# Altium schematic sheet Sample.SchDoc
size A3; SheetNumber: 3; SheetTotal: 4
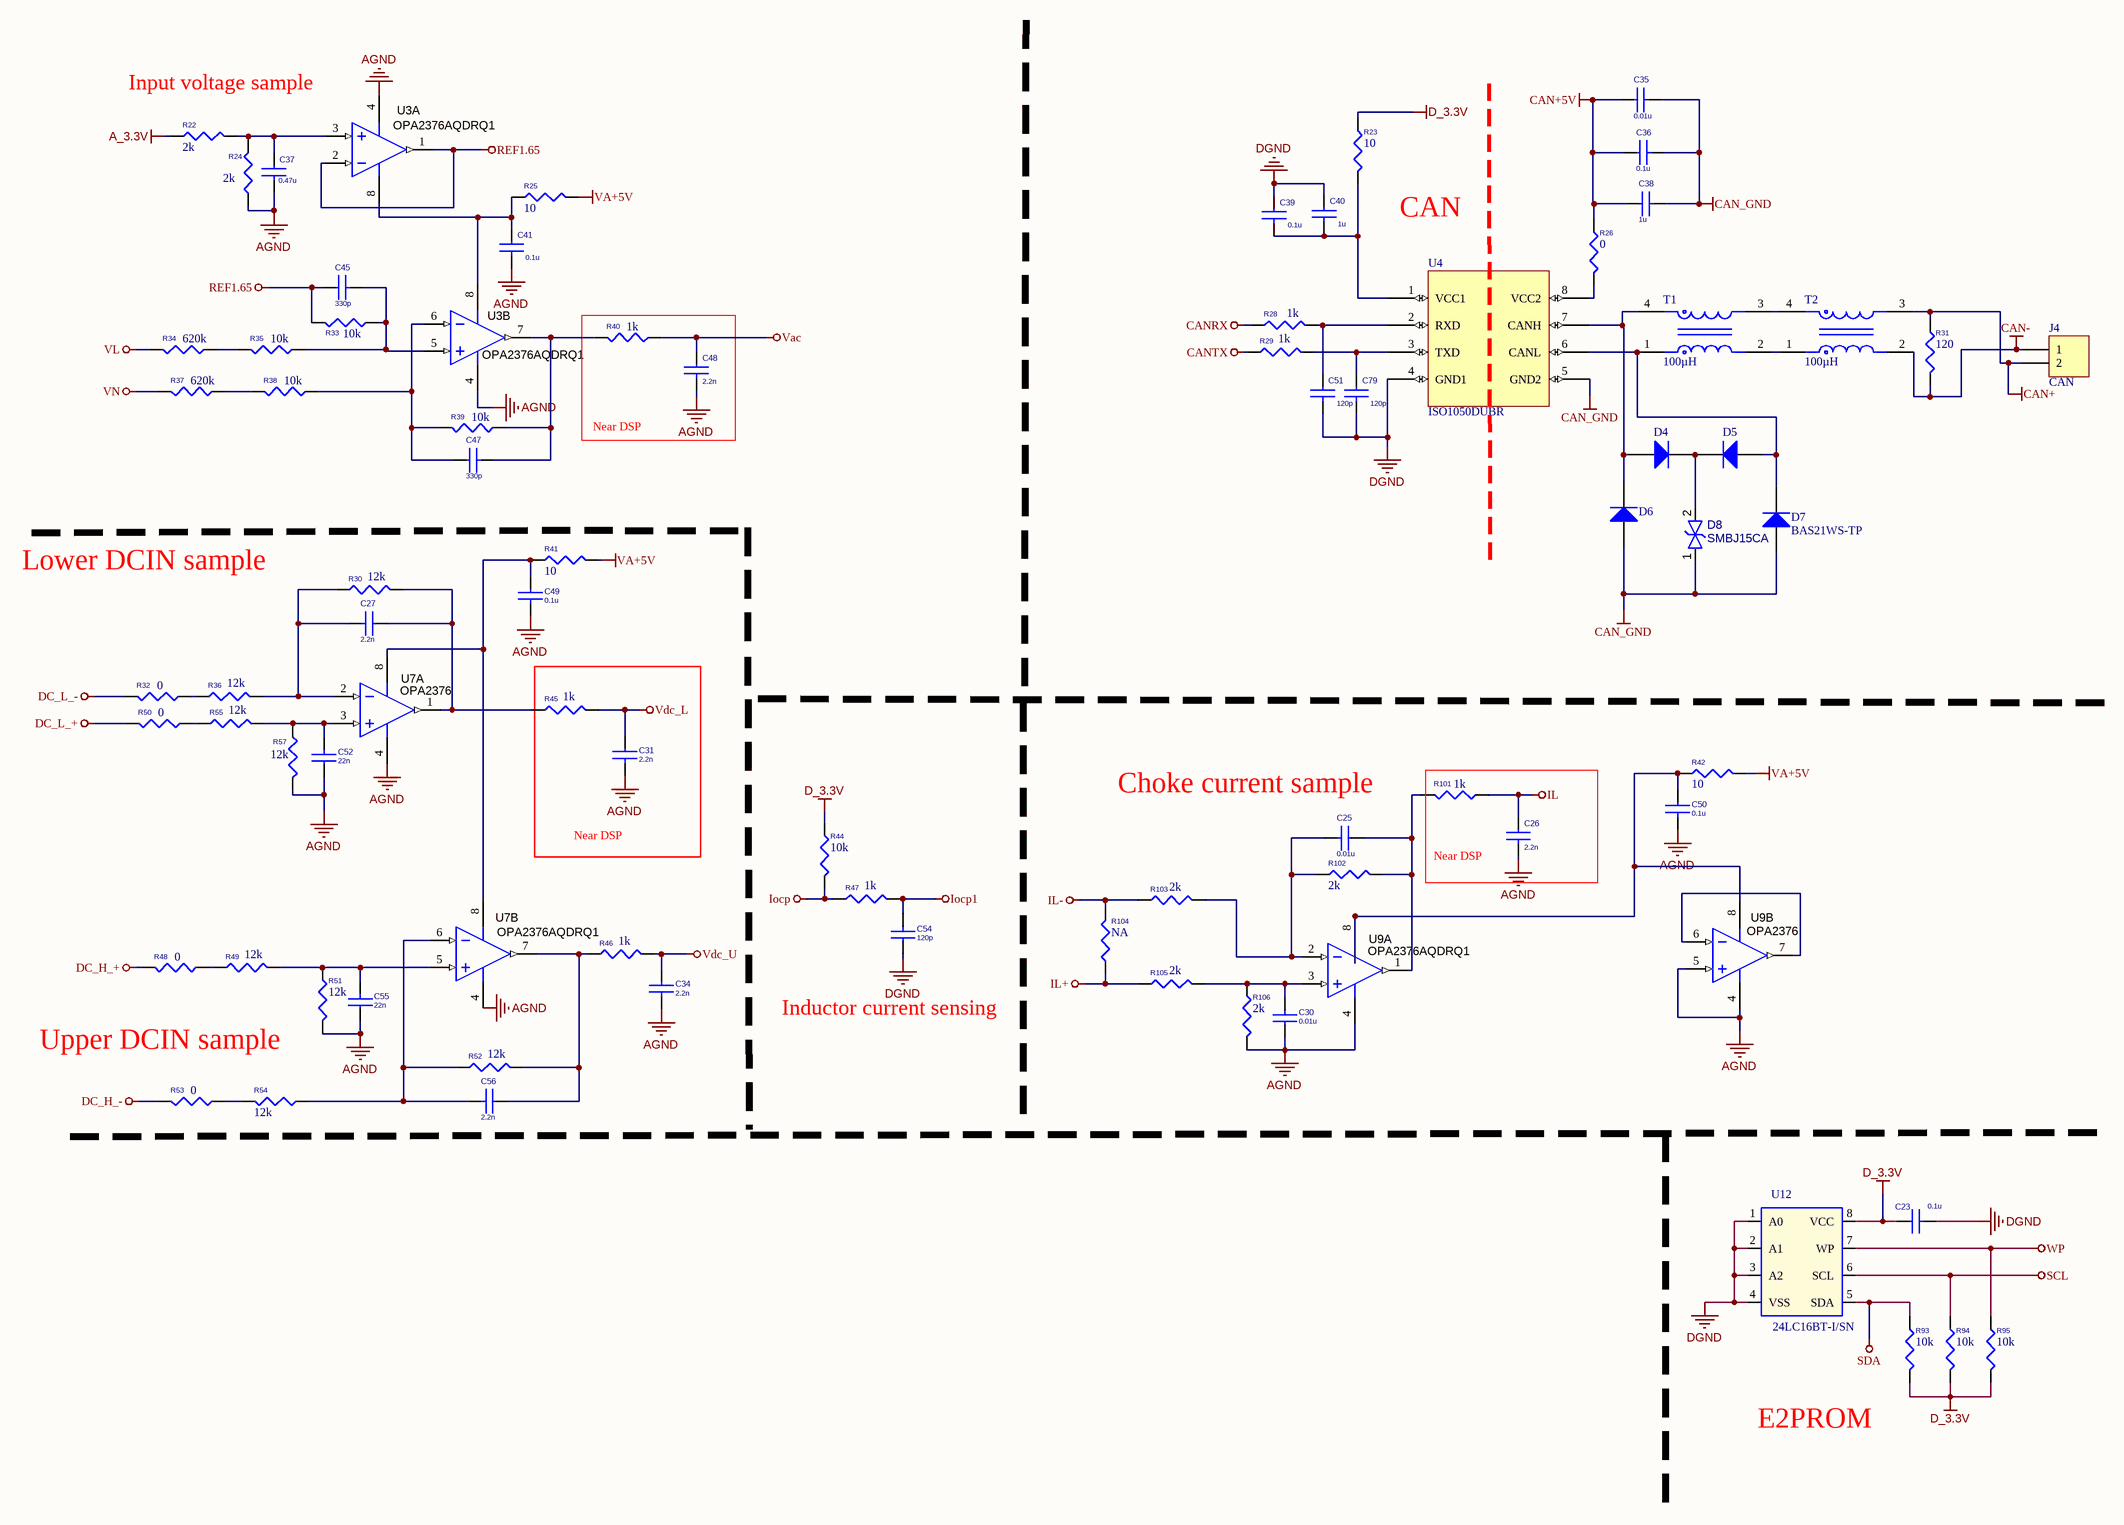
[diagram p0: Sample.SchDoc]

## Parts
C23  0.1u  [C0402]
C25  0.01u  [C0402]
C26  2.2n  [C0402]
C27  2.2n  [C0402]
C30  0.01u  [C0402]
C31  2.2n  [C0402]
C34  2.2n  [C0402]
C35  0.01u  [C0402]
C36  0.1u  [C0402]
C37  0.47u  [C0402]
C38  1u  [C0402]
C39  0.1u  [C0402]
C40  1u  [C0402]
C41  0.1u  [C0402]
C45  330p  [C0402]
C47  330p  [C0402]
C48  2.2n  [C0402]
C49  0.1u  [C0402]
C50  0.1u  [C0402]
C51  120p  [C0402]
C52  22n  [C0402]
C54  120p  [C0402]
C55  22n  [C0402]
C56  2.2n  [C0402]
C79  120p  [C0402]
D4  BAS21WS-TP  [DIOD-SOD323-2-A_V]  (value not drawn)
D5  BAS21WS-TP  [DIOD-SOD323-2-A_V]  (value not drawn)
D6  BAS21WS-TP  [DIOD-SOD323-2-A_V]  (value not drawn)
D7  BAS21WS-TP  [DIOD-SOD323-2-A_V]
D8  SMBJ15CA  [DO214AA]
J4  CAN  [HDR1X2H-254MM]
R22  2k  [R0402]
R23  10  [R0402]
R24  2k  [R0402]
R25  10  [R0402]
R26  0  [R0402]
R28  1k  [R0402]
R29  1k  [R0402]
R30  12k  [R0402]
R31  120  [R0603]
R32  0  [R1206]
R33  10k  [R0402]
R34  620k  [R1206]
R35  10k  [R1206]
R36  12k  [R1206]
R37  620k  [R1206]
R38  10k  [R1206]
R39  10k  [R0402]
R40  1k  [R0402]
R41  10  [R0402]
R42  10  [R0402]
R44  10k  [R0402]
R45  1k  [R0402]
R46  1k  [R0402]
R47  1k  [R0402]
R48  0  [R1206]
R49  12k  [R1206]
R50  0  [R1206]
R51  12k  [R0402]
R52  12k  [R0402]
R53  0  [R1206]
R54  12k  [R1206]
R55  12k  [R1206]
R57  12k  [R0402]
R93  10k  [R0402]
R94  10k  [R0402]
R95  10k  [R0402]
R101  1k  [R0402]
R102  2k  [R0402]
R103  2k  [R0402]
R104  NA  [R0402]
R105  2k  [R0402]
R106  2k  [R0402]
T1  AMCW4532B-2-101T: 100µH  [FP-DLW43-0_2-t2_6-e0_6-MFG]  (hidden comment: DLW43SH101XK2L)
T2  AMCW4532B-2-101T: 100µH  [FP-DLW43-0_2-t2_6-e0_6-MFG]  (hidden comment: DLW43SH101XK2L)
U3  OPA2376AQDRQ1  [8SOIC]  (parts A,B of 2)
U4  ISO1050DUBR  [8-SOP]
U7  OPA2376  [8SOIC]  (parts A,B of 2)
U9  OPA2376AQDRQ1  [8SOIC]  (parts A,B of 2)
U12  24LC16BT-I/SN  [8SOIC]

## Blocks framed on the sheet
Near DSP: C48 R40
Near DSP: C31 R45
Near DSP: C26 R101

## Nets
A_3.3V: R22.1
AGND: C26.2 C30.1 C31.2 C34.2 C37.2 C41.2 C48.2 C49.2 C50.2 C52.1 C55.1 R24.1 R51.2 R57.2 R106.2 U3.4(V-) U7.4(V-) U9.4(V-) U9.5(IN_B+)
CAN+: J4.2 R31.1 T2.3
CAN+5V: C35.1 C36.1 C38.1 R26.1
CAN-: J4.1 R31.2 T2.2
CAN_GND: C35.2 C36.2 C38.2 D6.1(A) D7.1(A) D8.1(A) U4.5(GND2)
CANRX: R28.1
CANTX: R29.1
D_3.3V: C23.1 R23.1 R44.1 R93.2 R94.2 R95.2 U12.8(VCC)
DC_H_+: R48.2
DC_H_-: R53.2
DC_L_+: R50.2
DC_L_-: R32.2
DGND: C23.2 C39.1 C40.1 C51.2 C54.1 C79.2 U4.4(GND1) U12.1(A0) U12.2(A1) U12.3(A2) U12.4(VSS)
IL: C26.1 R101.1
IL+: R104.1 R105.1
IL-: R103.1 R104.2
Iocp: R44.2 R47.1
Iocp1: C54.2 R47.2
REF1.65: C45.1 R33.2 U3.1(OUT_A) U3.2(IN_A-)
SCL: R94.1 U12.6(SCL)
SDA: R93.1 U12.5(SDA)
VA+5V: R25.2 R41.2 R42.2
Vac: C48.1 R40.1
Vdc_L: C31.1 R45.2
Vdc_U: C34.1 R46.2
VL: R34.2
VN: R37.2
WP: R95.1 U12.7(WP)
NetC25_1: C25.1 R101.2 R102.2 U9.1(OUT_A)
NetC25_2: C25.2 R102.1 R103.2 U9.2(IN_A-)
NetC27_1: C27.1 R30.2 R45.1 U7.1(OUT_A)
NetC27_2: C27.2 R30.1 R36.2 U7.2(IN_A-)
NetC30_2: C30.2 R105.2 R106.1 U9.3(IN_A+)
NetC37_1: C37.1 R22.2 R24.2 U3.3(IN_A+)
NetC39_2: C39.2 C40.2 R23.2 U4.1(VCC1)
NetC41_1: C41.1 R25.1 U3.8(V+)
NetC45_2: C45.2 R33.1 R35.1 U3.5(IN_B+)
NetC47_1: C47.1 R38.1 R39.2 U3.6(IN_B-)
NetC47_2: C47.2 R39.1 R40.2 U3.7(OUT_B)
NetC49_1: C49.1 R41.1 U7.8(V+)
NetC50_1: C50.1 R42.1 U9.8(V+)
NetC51_1: C51.1 R28.2 U4.2(RXD)
NetC52_2: C52.2 R55.2 R57.1 U7.3(IN_A+)
NetC55_2: C55.2 R49.2 R51.1 U7.5(IN_B+)
NetC56_1: C56.1 R46.1 R52.2 U7.7(OUT_B)
NetC56_2: C56.2 R52.1 R54.1 U7.6(IN_B-)
NetC79_1: C79.1 R29.2 U4.3(TXD)
NetD4_1: D4.1(A) D6.2(K) T1.4 U4.7(CANH)
NetD4_2: D4.2(K) D5.2(K) D8.2(A)
NetD5_1: D5.1(A) D7.2(K) T1.1 U4.6(CANL)
NetR26_2: R26.2 U4.8(VCC2)
NetR32_1: R32.1 R36.1
NetR34_1: R34.1 R35.2
NetR37_1: R37.1 R38.2
NetR48_1: R48.1 R49.1
NetR50_1: R50.1 R55.1
NetR53_1: R53.1 R54.2
NetT1_2: T1.2 T2.1
NetT1_3: T1.3 T2.4
NetU9_6: U9.6(IN_B-) U9.7(OUT_B)

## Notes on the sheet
- (near U3) Input voltage sample
- CAN
- Lower DCIN sample
- Choke current sample
- Upper DCIN sample
- Inductor current sensing
- E2PROM

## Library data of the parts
C23 = CAP NP_Dup1: CAP CER 0.1UF 25V X7R 0402; PCB Footprint: C0603
C25 C30 C35 = CAP NP_Dup1: CAP CER 0.012UF 25V X7R 0402; PCB Footprint: C1206
C26 C27 C31 C34 C48 C56 = CAP NP_Dup1: CAP CER 2200PF 25V X7R 0402; PCB Footprint: C1206
C36 C39 = CAP NP_Dup1: CCAP CER 0.1UF 25V X7R 0402; PCB Footprint: C1206
C37 = CAP NP_Dup1: CAP CER 0.47UF 25V X5R 0402; PCB Footprint: C1206
C38 C40 = CAP NP_Dup1: CAP CER 1UF 25V X5R 0402; PCB Footprint: C1206
C41 C49 C50 = CAP NP_Dup1: CAP CER 0.1UF 25V X7R 0402; PCB Footprint: C1206
C45 C47 = CAP NP_Dup1: CAP CER 330PF 25V X7R 0402; PCB Footprint: C1206
C51 C54 C79 = CAP NP_Dup1: CAP CER 120PF 25V C0G/NP0 0402; PCB Footprint: C1206
C52 C55 = CAP NP_Dup1: CAP CER 0.022UF 25V X7R 0402; PCB Footprint: C1206
D4-D7 = CMP-004-00002-1: DIODE GEN PURP 250V 200MA SOD323; Manufacturer: Diodes Inc; Peak Reverse Current: 1uA; Forward Voltage: 1.25V; Recovery Time: 4ns; Max Surge Current: 2A; Forward Current: 3dA; Elements: 1
D8 = CMP-004-00030-2: TVS DIODE 15V 24.4V DO214AA; Manufacturer: STMicroelectronics; Manufacturer Part Number: ESDALC5-1BM2
J4 = Header 2H: 1*2P 2.54mm
R22 R102 R103 R105 R106 = RESISTOR_Dup1: RCC0402 100 2K0 1% ET7 E3; PCB Footprint: R0603
R23 R25 R41 R42 = RESISTOR_Dup1: RES 10 OHM 1% 1/8W 0402; PCB Footprint: R0603
R24 = RESISTOR_Dup1: RES 3.9K OHM 1% 1/8W 0402; PCB Footprint: R0603
R26 R104 = RESISTOR_Dup1: PCB Footprint: R0603
R28 R29 R40 R45-R47 R101 = RESISTOR_Dup1: RES 1K OHM 1% 1/8W 0402; PCB Footprint: R0603
R30 R51 R52 R57 = RESISTOR_Dup1: RES 12K OHM 1% 1/8W 0402; PCB Footprint: R0603
R31 = RESISTOR_Dup1: RES SMD 120 OHM 1% 1/8W 0603
R32 R35 R38 R48 R50 R53 = RESISTOR_Dup1: RES 10K OHM 1% 1/4W 1206; PCB Footprint: R0603
R33 R39 R44 R93-R95 = RESISTOR_Dup1: RES 10K OHM 1% 1/8W 0402; PCB Footprint: R0603
R34 R37 = RESISTOR_Dup1: RES SMD 620K OHM 1% 1/10W 1206; PCB Footprint: R0603
R36 R49 R54 R55 = RESISTOR_Dup1: ES SMD 12K OHM 1% 1/4W 1206; PCB Footprint: R0603
T1 T2 = CMP-006-00021-2: CMC 100uH@1MHz 200MA 2LN SMD
U3 U9 = OPA2376AIDG4: Precision, Low Noise, Low Quiescent Current Operational Amplifier, 2 to 5.5 V, -40 to 125 degC, 8-pin SOIC (D0008A), Green (RoHS & no Sb/Br); Manufacturer: Texas Instruments; Alternate PartNumber: Equivalent; CMRR(Min)(dB): 76; IIB(Max)(pA): 10; Iq per channel(Max)(mA): 0.95; Number of Channels: 2; Offset Drift(Typ)(uV/C): 0.32; Sub Family: Low Input Bias Current Amp (<=10pA), Low Noise Amp (<=10nV/rtHz), Low Offset Voltage Amplifier (<=500uV), Low Supply Voltage Amplifier (<=2.7V), Precision Amplifier; Total Supply Voltage(Max)(+5V is 5, +/-5V is 10): 5.5; Vio (25C)(Max)(mV): 0.025; Vn at 1kHz(Typ)(nV/rtHz): 7.5
U4 = 1050: ISO1050 ISOLATED 5-V CAN TRANSCE
U7 = OPA2376AIDG4: Precision, Low Noise, Low Quiescent Current Operational Amplifier, 2 to 5.5 V, -40 to 125 degC, 8-pin SOIC (D0008A), Green (RoHS & no Sb/Br); Manufacturer: Texas Instruments; PartNumber: OPA2376AQDRQ1; Alternate PartNumber: Equivalent; CMRR(Min)(dB): 76; IIB(Max)(pA): 10; Iq per channel(Max)(mA): 0.95; Number of Channels: 2; Offset Drift(Typ)(uV/C): 0.32; Sub Family: Low Input Bias Current Amp (<=10pA), Low Noise Amp (<=10nV/rtHz), Low Offset Voltage Amplifier (<=500uV), Low Supply Voltage Amplifier (<=2.7V), Precision Amplifier; Total Supply Voltage(Max)(+5V is 5, +/-5V is 10): 5.5; Vio (25C)(Max)(mV): 0.025; Vn at 1kHz(Typ)(nV/rtHz): 7.5
U12 = 24C16BT-I/SN: IC EEPROM 16K I2C 1MHZ 8SOIC; PCB Footprint: SOIC-8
